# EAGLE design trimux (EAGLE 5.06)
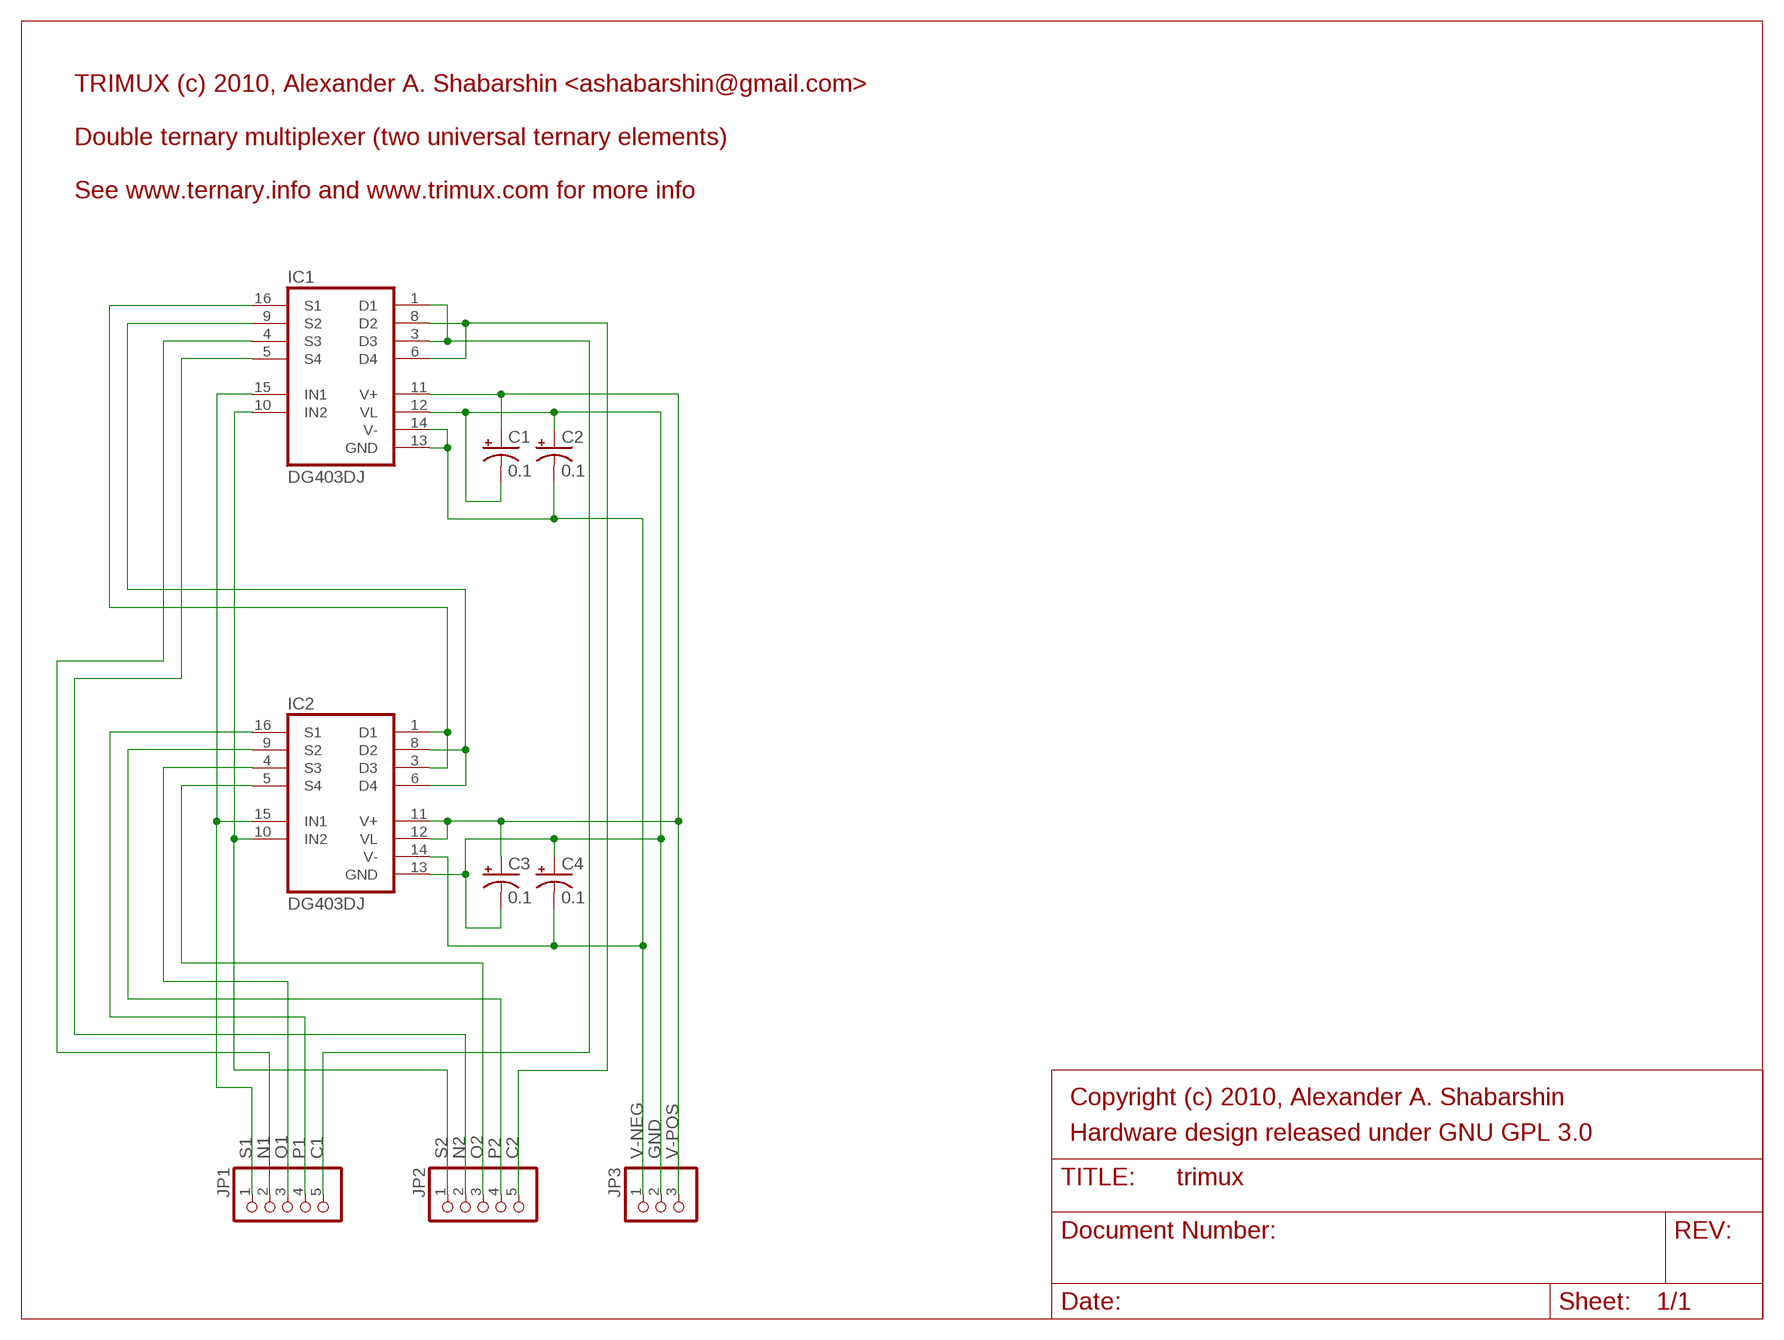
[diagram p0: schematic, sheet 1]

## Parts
C1  0.1  CPOL-USB45181A  [B45181A]
C2  0.1  CPOL-USB45181A  [B45181A]
C3  0.1  CPOL-USB45181A  [B45181A]
C4  0.1  CPOL-USB45181A  [B45181A]
IC1  DG403DJ  [DIL16]
IC2  DG403DJ  [DIL16]
JP1  PINHD-1X5  [1X05]
JP2  PINHD-1X5  [1X05]
JP3  PINHD-1X3  [1X03]

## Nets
C1: IC1.1(D1) IC1.3(D3) JP1.5
C2: IC1.6(D4) IC1.8(D2) JP2.5
GND: C1.- C2.+ C3.- C4.+ IC1.12(VL) IC2.13(GND) JP3.2
N1: IC1.4(S3) JP1.2
N2: IC1.5(S4) JP2.2
N$5: IC1.16(S1) IC2.1(D1) IC2.3(D3)
N$6: IC1.9(S2) IC2.6(D4) IC2.8(D2)
O1: IC2.4(S3) JP1.3
O2: IC2.5(S4) JP2.3
P1: IC2.16(S1) JP1.4
P2: IC2.9(S2) JP2.4
S1: IC1.15(IN1) IC2.15(IN1) JP1.1
S2: IC1.10(IN2) IC2.10(IN2) JP2.1
V-NEG: C2.- C4.- IC1.13(GND) IC1.14(V-) IC2.14(V-) JP3.1
V-POS: C1.+ C3.+ IC1.11(V+) IC2.11(V+) IC2.12(VL) JP3.3

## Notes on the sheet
- TRIMUX (c) 2010, Alexander A. Shabarshin <ashabarshin@gmail.com>
- Double ternary multiplexer (two universal ternary elements)
- See www.ternary.info and www.trimux.com for more info
- Copyright (c) 2010, Alexander A. Shabarshin
- Hardware design released under GNU GPL 3.0

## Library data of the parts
C1-C4 = rcl:CPOL-US: POLARIZED CAPACITOR, American symbol
IC1 IC2 = maxim:DG403DJ: ANALOG SWITCH
JP1 JP2 = pinhead:PINHD-1X5: PIN HEADER
JP3 = pinhead:PINHD-1X3: PIN HEADER

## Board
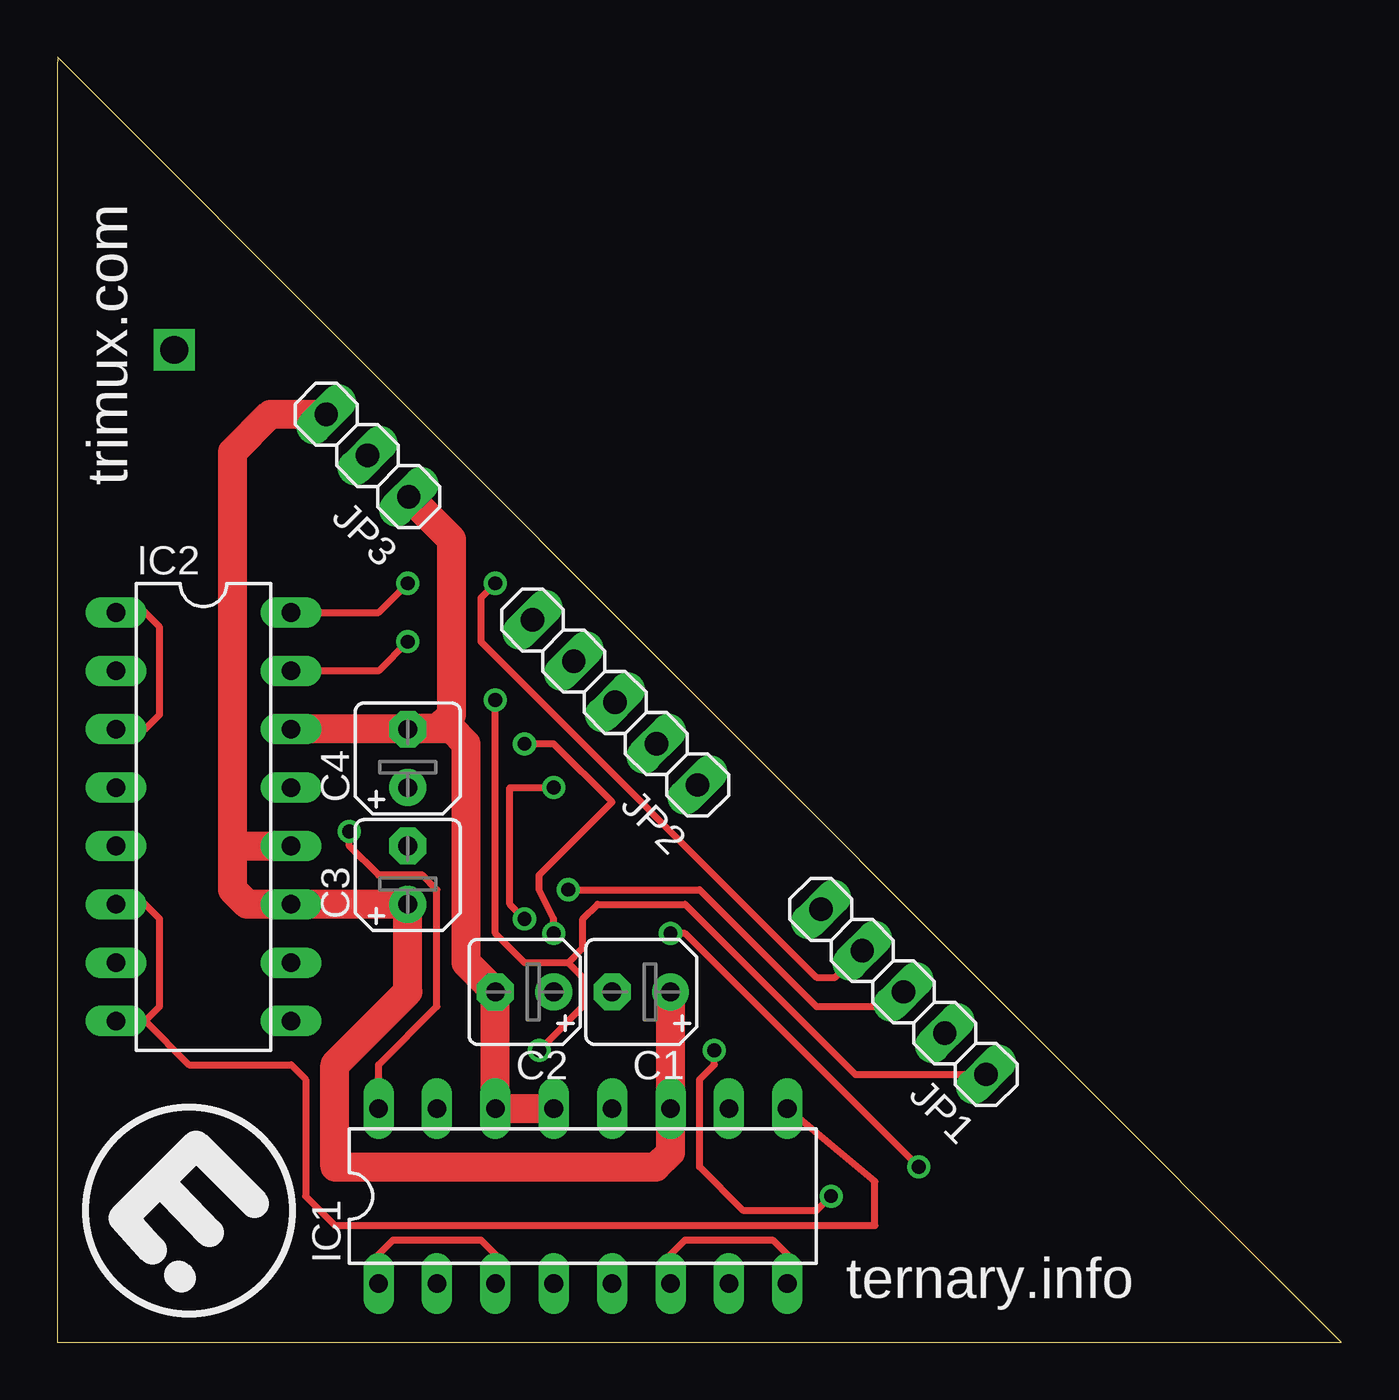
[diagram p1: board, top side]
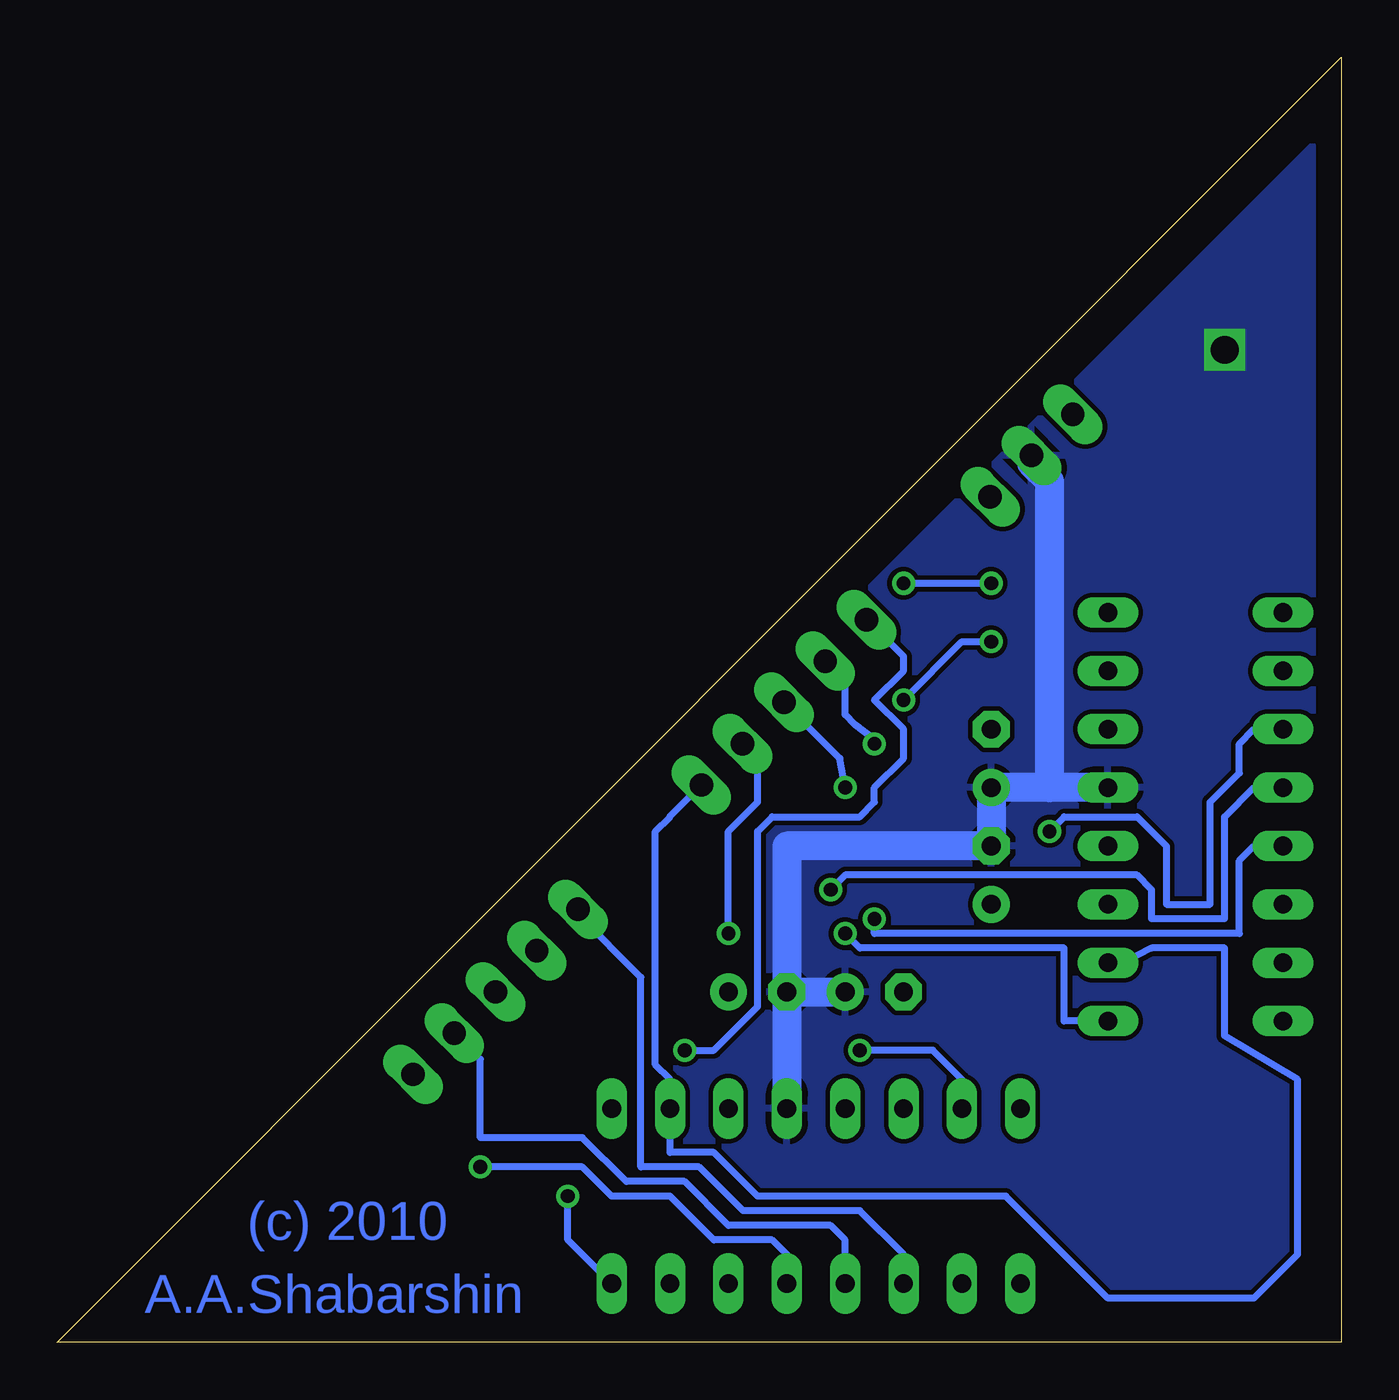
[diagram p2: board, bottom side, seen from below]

Size 55.86 x 55.91 mm. Coordinates in mm from the lower left corner, seen from the top.
Outline: 0,0 55.86,0 0.01,55.91 0,55.55 0,0
Copper layers (1*16): Top 0.035mm / dielectric 1.5mm / Bottom 0.035mm
Design rules "default *": minimum track width 10mil, minimum drill 20mil, track to track 8mil, track to pad 8mil, pad to pad 8mil, via to via 8mil, smd to smd 8mil, copper to edge 40mil, drill to drill 8mil, minimum pad ring 10mil, minimum via ring 8mil, stop-mask expansion 4mil, vias tented up to drill 0mil, thermal gap 10mil

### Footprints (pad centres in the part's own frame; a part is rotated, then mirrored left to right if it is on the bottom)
B45181A = drill 0.813 pad 1.6 round: + -1.27,0 | drill 0.813 pad 1.6 octagon: - 1.27,0
DIL16 = drill 0.813 long: 1 -8.89,-3.81; 2 -6.35,-3.81; 3 -3.81,-3.81; 4 -1.27,-3.81; 5 1.27,-3.81; 6 3.81,-3.81; 7 6.35,-3.81; 8 8.89,-3.81; 9 8.89,3.81; 10 6.35,3.81; 11 3.81,3.81; 12 1.27,3.81; 13 -1.27,3.81; 14 -3.81,3.81; 15 -6.35,3.81; 16 -8.89,3.81
1X05 = drill 1.016 long: 1 -5.08,0; 2 -2.54,0; 3 0,0; 4 2.54,0; 5 5.08,0
1X03 = drill 1.016 long: 1 -2.54,0; 2 0,0; 3 2.54,0

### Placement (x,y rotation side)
C1  25.4,15.24 180 top
C2  20.32,15.24 180 top
C3  15.24,20.32 90 top
C4  15.24,25.4 90 top
IC1  22.86,6.35 0 top
IC2  6.35,22.86 270 top
JP1  36.8,15.24 135 top
JP2  24.26,27.84 135 top
JP3  13.49,38.58 135 top

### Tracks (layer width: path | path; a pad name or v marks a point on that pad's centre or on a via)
C1
  Top 0.305: IC1.1 13.97,3.81 14.61,4.45 18.41,4.45 19.05,3.81 IC1.3
  Bottom 0.305: JP1.5 33.21,18.61 30.48,15.88 30.48,7.62 27.94,7.62 26.04,5.71 20.95,5.71 19.05,3.81 IC1.3
C2  (via drill 0.6)
  Top 0.305: IC1.6 26.67,3.81 27.3,4.45 31.11,4.45 31.75,3.81 IC1.8 | v28.57,12.7 28.57,12.06 27.94,11.43 27.94,7.62 29.84,5.71 33.02,5.71 v33.66,6.35
  Bottom 0.305: JP2.5 20.64,31.43 19.05,29.84 19.05,29.21 20.32,27.94 19.05,26.67 19.05,25.4 20.32,24.13 20.32,23.5 20.95,22.86 24.77,22.86 25.4,22.23 25.4,14.61 27.3,12.7 v28.57,12.7 | v33.66,6.35 33.66,4.45 IC1.8
GND  (via drill 1.2)
  Bottom 1.27: JP3.2 13.49,38.25 12.7,37.47 12.7,24.13 | IC2.13 12.7,24.13 | 12.7,24.13 C4.+ C3.- 24.13,21.59 C1.- | C1.- IC1.12 | C1.- C2.+ C1.-
  other vias: 5.08,43.18
  pour Bottom: 1.27,52.07 1.27,2.54 2.54,1.27 51.44,1.27 51.44,1.91
N1
  Bottom 0.305: IC1.4 21.59,4.45 22.23,5.08 26.67,5.08 28.57,6.99 31.11,6.99 33.02,8.89 37.47,8.89 37.47,12.31 JP1.2
N2  (via drill 0.6)
  Top 0.305: v37.47,7.62 27.3,17.78 v26.67,17.78
  Bottom 0.305: IC1.5 24.13,3.81 24.77,4.45 27.3,4.45 29.21,6.35 31.75,6.35 33.02,7.62 v37.47,7.62 | v26.67,17.78 26.67,22.23 25.4,23.5 25.4,25.39 JP2.2
N$5  (via drill 0.6)
  Top 0.305: IC2.1 3.81,31.75 4.45,31.11 4.45,27.3 3.81,26.67 IC2.3 | v12.7,22.23 12.7,21.59 13.97,20.32 15.88,20.32 16.51,19.68 16.51,14.61 13.97,12.06 IC1.16
  Bottom 0.305: IC2.3 3.81,26.67 4.45,26.04 4.45,24.77 5.71,23.5 5.71,19.05 7.62,19.05 7.62,21.59 8.89,22.86 12.06,22.86 v12.7,22.23
N$6
  Top 0.305: IC2.6 3.81,19.05 4.45,18.41 4.45,14.61 3.81,13.97 | IC2.8 3.81,13.97 | 3.81,13.97 5.71,12.06 10.16,12.06 10.79,11.43 10.79,6.35 12.06,5.08 35.56,5.08 35.56,6.99 IC1.9
O1  (via drill 0.6)
  Top 0.305: v22.23,19.68 27.94,19.68 33.02,14.61 36.17,14.61 JP1.3
  Bottom 0.305: IC2.4 3.81,24.13 5.08,22.86 5.08,18.41 8.26,18.41 8.26,19.68 8.89,20.32 21.59,20.32 v22.23,19.68
O2  (via drill 0.6)
  Top 0.305: v20.32,18.41 19.68,19.05 19.68,24.13 v21.59,24.13
  Bottom 0.305: IC2.5 3.81,21.59 4.45,20.95 4.45,17.78 20.32,17.78 v20.32,18.41 | v21.59,24.13 21.82,25.4 JP2.3
P1  (via drill 0.6)
  Top 0.305: IC2.16 13.97,31.75 v15.24,33.02 | v19.05,33.02 18.41,32.38 18.41,30.48 33.02,15.88 33.85,15.88 JP1.4
  Bottom 0.305: v15.24,33.02 v19.05,33.02
P2  (via drill 0.6)
  Top 0.305: v21.59,17.78 21.59,18.41 20.95,19.68 20.95,20.32 24.13,23.5 21.59,26.04 v20.32,26.04
  Bottom 0.305: IC2.9 12.06,13.97 12.06,17.14 20.95,17.14 v21.59,17.78 | v20.32,26.04 20.32,26.22 21.14,26.86 21.59,27.3 21.59,28.57 JP2.4
S1  (via drill 0.6)
  Top 0.305: IC2.15 13.97,29.21 v15.24,30.48 | v19.05,27.94 19.05,17.78 20.32,16.51 22.23,16.51 | 22.23,16.51 22.86,15.88 22.86,14.61 v20.95,12.7 | JP1.1 34.71,11.65 27.3,19.05 23.5,19.05 22.86,18.41 22.86,17.14 22.23,16.51
  Bottom 0.305: v15.24,30.48 16.51,30.48 v19.05,27.94 | v20.95,12.7 17.78,12.7 16.51,11.43 IC1.15
S2
  Bottom 0.305: IC2.10 9.53,16.51 8.26,17.14 5.08,17.14 5.08,13.34 1.91,11.43 1.91,3.81 3.81,1.91 10.16,1.91 14.61,6.35 25.4,6.35 27.3,8.26 29.21,8.26 IC1.10 29.21,11.43 29.84,12.06 29.84,22.23 29.21,22.86 29.21,22.89 JP2.1
V-NEG
  Top 1.27: JP3.1 17.14,34.92 17.14,27.3 16.55,26.71 15.28,26.71 C4.- | C4.- IC2.14 | C4.- 17.14,26.67 17.78,26.04 17.78,16.51 C2.- IC1.14 IC1.13
V-POS
  Top 1.27: JP3.3 9.26,40.38 7.62,38.73 7.62,21.59 | 7.62,21.59 7.62,19.68 8.26,19.05 IC2.11 C3.+ 15.24,15.24 12.06,12.06 12.06,7.62 26.04,7.62 26.67,8.26 IC1.11 C1.+ | 7.62,21.59 IC2.12

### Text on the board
Bottom: (c) 2010 | A.A.Shabarshin
tNames: trimux.com | ternary.info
